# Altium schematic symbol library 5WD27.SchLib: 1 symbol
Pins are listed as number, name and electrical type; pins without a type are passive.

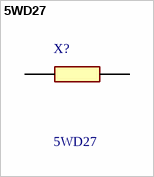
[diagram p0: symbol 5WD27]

## 5WD27
designator X?
Res Wirewound 270 Ohm 5% 5W +/-300ppm/C Molded AXL; Manufacturer_Name: NTE ELECTRONICS; Geometry.Height: 9.65mm
footprint 5WD27
pins: 1, 2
